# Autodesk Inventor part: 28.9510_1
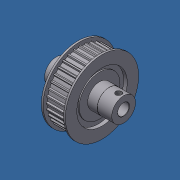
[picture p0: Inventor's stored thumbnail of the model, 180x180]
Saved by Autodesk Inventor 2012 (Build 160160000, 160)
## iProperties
Created: 2007-06
Part Number: 28.9510_1
Document SubType Name: Modeling
Designer: Andy Moles
Material: Aluminum-6061
Density: 2.71 g/cm^3
Mass: 139.144 g
Surface Area: 162.293 cm^2
Volume: 51.3448 cm^3
Description: TIMING BELT PULLEY LR6 PULLEY  .375in
Author: Andy Moles
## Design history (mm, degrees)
sketch "Sketch1"
  geometry: L1 (-28, 4)-(-28, 9.9); L2 (-28, 9.9)-(-16, 9.9); L3 (-8, 10)-(-8, 21); L4 (-8, 21)-(-10, 21); L5 (-10, 21)-(-10, 30.5); L6 (-10, 30.5)-(-8.5, 30.5); L7 (-8.5, 30.5)-(-8.5, 26.8); L8 (-8.5, 26.8)-(8.5, 26.8); L9 (8.5, 26.8)-(8.5, 30.5); L10 (8.5, 30.5)-(10, 30.5); L11 (10, 30.5)-(10, 21); L12 (10, 21)-(8, 21); L13 (8, 21)-(8, 10); L14 (16, 9.9)-(28, 9.9); L15 (28, 9.9)-(28, 4); L16 (28, 4)-(-28, 4); L17 (0, 0)-(51.814, 0); L18 (-16, 9.9)-(-16, 10); L19 (-16, 10)-(-8, 10); L20 (16, 9.9)-(16, 10); L21 (16, 10)-(8, 10); 2 further points
  constraints: 42 end point, 12 parallel, 7 perpendicular, 5 equal length, 4 horizontal alignment, 2 midpoint, 2 vertical alignment, 1 horizontal, 1 point on line, 1 vertical
  dimensions: "d0" = 56 distance of L15.end L1.start; "d1" = 20 distance between parallel lines of L11 L5; "d2" = 2 distance of L11.end L12.end; "d3" = 4 distance from line of L16 L17.start (= 0.5 x BORE_DIA); "d4" = 9.9 distance from line of L2 L17.start; "d5" = 21 distance from line of L4 L17.start; "d6" = 17 distance between parallel lines of L9 L7; "d7" = 3.7 distance between parallel lines of L8 L6; "d8" = 26.8 distance from line of L8 L17.start; "d23" = 12 distance between parallel lines of L18 L1; "d24" = 10 distance from line of L19 L17.start
revolve "Revolution1" sketch "Sketch1" stored, may be unused: angle "d9" = 90 deg
sketch "Sketch2"
  geometry: L1 (0, 0)-(0, 40.828); L2 (-1.05, 26.779)-(-0.49, 27.979); L3 (-0.49, 27.979)-(0.49, 27.979); L4 (0.49, 27.979)-(1.05, 26.779); C1 r 30.5 at (0, 0) reference; A1 r 26.8 centre (0, 0) between (-1.05, 26.779) and (1.05, 26.779) reference; 1 further point
  constraints: 8 end point, 2 point on circle, 1 midpoint, 1 perpendicular, 1 point on line, 1 vertical
  dimensions: "d10" = 50 deg angle of L4 L2; "d11" = 25 deg angle of L1 L2; "d13" = 1.2 distance from line of L3 L2.start; "d14" = 2.1 distance of L4.end L2.start
extrude "Extrusion1" join sketch "Sketch2" distance "d15" = 17; taper "d16" = 0 deg
sketch "Sketch3"
  geometry: C1 r 9.9 at (0, 0) reference; C2 r 21 at (0, 0) reference; C3 r 17 at (0, 0)
  constraints: 1 centre point, 1 coincident
  dimensions: "d20" = 34 diameter of C3
extrude "Extrusion2" cut sketch "Sketch3" distance "d21" = 1; taper "d22" = 0 deg
mirror "Mirror1"
sketch "Sketch4"
  geometry: C1 r 4 at (0, 0) reference; C2 r 9.9 at (0, 0) reference; C3 r 4.763 at (0, 0)
  constraints: 1 centre point, 1 coincident
  dimensions: "d25" = 9.525 diameter of C3
extrude "Extrusion3" cut sketch "Sketch4" stored distance "d26" = 10; taper "d27" = 0 deg
sketch "Sketch5"
  geometry: L1 (28, -9.9)-(28, 9.9) reference; C1 r 2.5 at (24, 0); 2 further points
  constraints: 1 centre point, 1 horizontal alignment, 1 midpoint
  dimensions: "d28" = 5 diameter of C1; "d29" = 4 distance from line of C1.centre L1
extrude "Extrusion4" cut sketch "Sketch5" stored distance "d30" = 10; taper "d31" = 0 deg
thread "Thread2" dims "d34" = 10, "d35" = 0
chamfer "Chamfer1" distance "d36" = 0.254; stored, may be unused: second distance "d37" = 2, angle "d38" = 45 deg
body "Solid1"
pattern_circular "Circular Pattern1" dims angle "d18" = 360 deg
other parameters: "BORE_DIA" = 8 [user parameter; used in 1 equation term]
